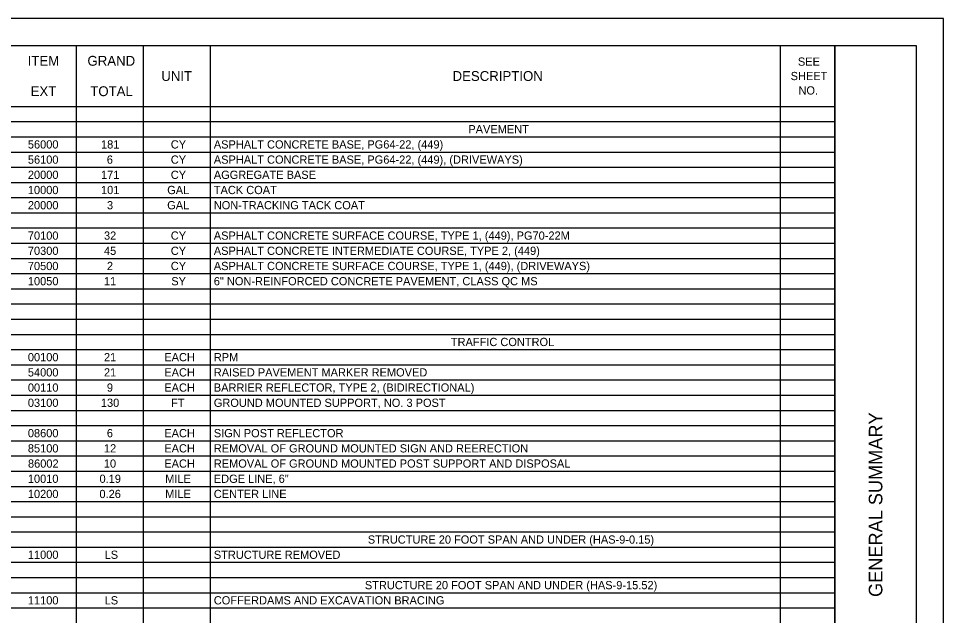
# Model space of a CAD drawing. Extents: x 0 to 1700, y 0 to 1100.
# Drawn here: x 849 to 1700, y 550 to 1100 of the extents above; entities that cross this region are included whole.
import ezdxf

# ---------------------------------------------------------------- set-up
doc = ezdxf.new("R2010")
doc.units = 0
for name, color, linetype in [('SH_Border', 7, 'Continuous'), ('SH_Cut_Line', 7, 'Continuous'), ('SH_Data', 7, 'Continuous'), ('SH_Text', 7, 'Continuous')]:
    doc.layers.add(name, color=color, linetype=linetype)

msp = doc.modelspace()

# ---------------------------------------------------------------- linework, layer by layer
at = {"layer": 'SH_Border'}
msp.add_line((1600, 25), (1600, 1075), dxfattribs=at)
msp.add_lwpolyline([(75, 1075), (1675, 1075), (1675, 25), (75, 25)], close=True, dxfattribs=at)
at = {"layer": 'SH_Cut_Line'}
msp.add_lwpolyline([(0, 0), (1700, 0), (1700, 1100), (0, 1100)], close=True, dxfattribs=at)
at = {"layer": 'SH_Text'}
for p, q in [((75, 1075), (1600, 1075)), ((901.73, 1075), (901.73, 25.12)), ((963.49, 1075), (963.49, 25.12)), ((1025.24, 1075), (1025.24, 25.12)), ((1549.77, 1075), (1549.77, 25.12)), ((1600, 1075), (1600, 25.12)), ((75, 1019.01), (1600, 1019.01)), ((75, 1005.01), (1600, 1005.01)), ((75, 991.01), (1600, 991.01)), ((75, 977.01), (1600, 977.01)), ((75, 963.01), (1600, 963.01)), ((75, 949.01), (1600, 949.01)), ((75, 935.02), (1600, 935.02)), ((75, 921.02), (1600, 921.02)), ((75, 907.02), (1600, 907.02)), ((75, 893.02), (1600, 893.02)), ((75, 879.02), (1600, 879.02)), ((75, 865.02), (1600, 865.02)), ((75, 851.03), (1600, 851.03)), ((75, 837.03), (1600, 837.03)), ((75, 823.03), (1600, 823.03)), ((75, 809.03), (1600, 809.03)), ((75, 795.03), (1600, 795.03)), ((75, 781.03), (1600, 781.03)), ((75, 767.04), (1600, 767.04)), ((75, 753.04), (1600, 753.04)), ((75, 739.04), (1600, 739.04)), ((75, 725.04), (1600, 725.04)), ((75, 711.04), (1600, 711.04)), ((75, 697.04), (1600, 697.04)), ((75, 683.05), (1600, 683.05)), ((75, 669.05), (1600, 669.05)), ((75, 655.05), (1600, 655.05)), ((75, 641.05), (1600, 641.05)), ((75, 627.05), (1600, 627.05)), ((75, 613.05), (1600, 613.05)), ((75, 599.06), (1600, 599.06)), ((75, 585.06), (1600, 585.06)), ((75, 571.06), (1600, 571.06)), ((75, 557.06), (1600, 557.06))]:
    msp.add_line(p, q, dxfattribs=at)

# ---------------------------------------------------------------- texts
at = {"layer": 'SH_Data'}
msp.add_text('GENERAL SUMMARY', height=12.5, rotation=90, dxfattribs=at).set_placement((1643.75, 567.18))
at = {"layer": 'SH_Text'}
for s, height, p in [('ITEM', 9.091, (857.27, 1056.46)), ('GRAND', 9.091, (912.27, 1056.46)), ('SEE ', 7.576, (1566.01, 1056.47)), ('UNIT', 9.091, (980.2, 1042.46)), ('DESCRIPTION', 9.0907, (1248.23, 1042.46)), ('SHEET ', 7.576, (1559.34, 1043.22)), ('EXT', 9.091, (859.97, 1028.46)), ('TOTAL', 9.091, (914.86, 1028.46)), ('NO.', 7.576, (1566.56, 1029.96)), ('PAVEMENT', 7.576, (1262.76, 994.22)), ('56000', 7.576, (857.43, 980.22)), ('181', 7.576, (924.74, 980.22)), ('CY', 7.576, (988.96, 980.22)), ('ASPHALT CONCRETE BASE, PG64-22, (449)', 7.5756, (1028.54, 980.22)), ('56100', 7.576, (857.43, 966.22)), ('6', 7.58, (930.1, 966.22)), ('CY', 7.576, (988.96, 966.22)), ('ASPHALT CONCRETE BASE, PG64-22, (449), (DRIVEWAYS)', 7.5756, (1028.54, 966.22)), ('20000', 7.576, (857.43, 952.23)), ('171', 7.576, (924.74, 952.23)), ('CY', 7.576, (988.96, 952.23)), ('AGGREGATE BASE', 7.5756, (1028.54, 952.23)), ('10000', 7.576, (857.43, 938.23)), ('101', 7.576, (924.74, 938.23)), ('GAL', 7.576, (985.65, 938.23)), ('TACK COAT', 7.576, (1028.54, 938.23)), ('20000', 7.576, (857.43, 924.23)), ('3', 7.58, (930.21, 924.23)), ('GAL', 7.576, (985.65, 924.23)), ('NON-TRACKING TACK COAT', 7.5756, (1028.54, 924.23)), ('70100', 7.576, (857.43, 896.23)), ('32', 7.576, (927.46, 896.23)), ('CY', 7.576, (988.96, 896.23)), ('ASPHALT CONCRETE SURFACE COURSE, TYPE 1, (449), PG70-22M', 7.5756, (1028.54, 896.23)), ('70300', 7.576, (857.43, 882.23)), ('45', 7.576, (927.48, 882.23)), ('CY', 7.576, (988.96, 882.23)), ('ASPHALT CONCRETE INTERMEDIATE COURSE, TYPE 2, (449)', 7.5756, (1028.54, 882.23)), ('70500', 7.576, (857.43, 868.24)), ('2', 7.58, (930.18, 868.24)), ('CY', 7.576, (988.96, 868.24)), ('ASPHALT CONCRETE SURFACE COURSE, TYPE 1, (449), (DRIVEWAYS)', 7.5756, (1028.54, 868.24)), ('10050', 7.576, (857.43, 854.24)), ('11', 7.576, (927.46, 854.24)), ('SY', 7.576, (989.41, 854.24)), ('6" NON-REINFORCED CONCRETE PAVEMENT, CLASS QC MS', 7.5756, (1028.54, 854.24)), ('TRAFFIC CONTROL', 7.5756, (1246.67, 798.24)), ('00100', 7.576, (857.43, 784.25)), ('21', 7.576, (927.46, 784.25)), ('EACH', 7.576, (982.97, 784.25)), ('RPM', 7.576, (1028.54, 784.25)), ('54000', 7.576, (857.43, 770.25)), ('21', 7.576, (927.46, 770.25)), ('EACH', 7.576, (982.97, 770.25)), ('RAISED PAVEMENT MARKER REMOVED', 7.5756, (1028.54, 770.25)), ('00110', 7.576, (857.43, 756.25)), ('9', 7.58, (930.16, 756.25)), ('EACH', 7.576, (982.97, 756.25)), ('BARRIER REFLECTOR, TYPE 2, (BIDIRECTIONAL)', 7.5756, (1028.54, 756.25)), ('03100', 7.576, (857.43, 742.25)), ('130', 7.576, (924.63, 742.25)), ('FT', 7.576, (989.32, 742.25)), ('GROUND MOUNTED SUPPORT, NO. 3 POST', 7.5756, (1028.54, 742.25)), ('08600', 7.576, (857.43, 714.25)), ('6', 7.58, (930.1, 714.25)), ('EACH', 7.576, (982.97, 714.25)), ('SIGN POST REFLECTOR', 7.5756, (1028.54, 714.25)), ('85100', 7.576, (857.43, 700.26)), ('12', 7.576, (927.46, 700.26)), ('EACH', 7.576, (982.97, 700.26)), ('REMOVAL OF GROUND MOUNTED SIGN AND REERECTION', 7.5756, (1028.54, 700.26)), ('86002', 7.576, (857.54, 686.26)), ('10', 7.576, (927.35, 686.26)), ('EACH', 7.576, (982.97, 686.26)), ('REMOVAL OF GROUND MOUNTED POST SUPPORT AND DISPOSAL', 7.5756, (1028.54, 686.26)), ('10010', 7.576, (857.43, 672.26)), ('0.19', 7.576, (923.36, 672.26)), ('MILE', 7.576, (983.82, 672.26)), ('EDGE LINE, 6"', 7.5756, (1028.54, 672.26)), ('10200', 7.576, (857.43, 658.26)), ('0.26', 7.576, (923.3, 658.26)), ('MILE', 7.576, (983.82, 658.26)), ('CENTER LINE', 7.5756, (1028.54, 658.26)), ('STRUCTURE 20 FOOT SPAN AND UNDER (HAS-9-0.15)', 7.5756, (1170.26, 616.26)), ('11000', 7.576, (857.43, 602.27)), ('LS', 7.576, (928.08, 602.27)), ('STRUCTURE REMOVED', 7.5756, (1028.54, 602.27)), ('STRUCTURE 20 FOOT SPAN AND UNDER (HAS-9-15.52)', 7.5756, (1167.54, 574.27)), ('11100', 7.576, (857.43, 560.27)), ('LS', 7.576, (928.08, 560.27)), ('COFFERDAMS AND EXCAVATION BRACING', 7.5756, (1028.54, 560.27))]:
    msp.add_text(s, height=height, dxfattribs=at).set_placement(p)

doc.saveas('drawing.dxf')
